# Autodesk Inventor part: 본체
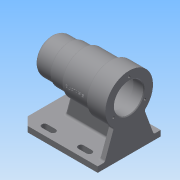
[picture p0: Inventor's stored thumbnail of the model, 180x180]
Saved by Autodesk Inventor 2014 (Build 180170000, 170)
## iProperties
Created: 2017-09
Part Number: 본체
Material: 일반
Document SubType Name: Modeling
Designer: net
Density: 1 g/cm^3
Appearance: 기본값
Author: net
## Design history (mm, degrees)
sketch "스케치1"
  geometry: L1 (56, 0)-(-56, 0); L2 (56, 0)-(56, 25); L3 (56, 25)-(31, 25); L4 (31, 25)-(31, 27); L5 (31, 27)-(11, 27); L6 (11, 27)-(11, 30); L7 (11, 30)-(-28, 30); L8 (-28, 30)-(-28, 34); L9 (-28, 34)-(-56, 34); L10 (-56, 21)-(-41, 21); L11 (-41, 21)-(-41, 21); L12 (-38, 24)-(10, 24); L13 (13, 21)-(13, 21); L14 (13, 21)-(24.7, 21); L15 (25, 20.7)-(25, 17.5); L16 (25, 17.5)-(42.7, 17.5); L17 (43, 17.2)-(43, 16); L18 (43, 16)-(46.7, 16); L19 (47, 15.7)-(47, 10.5); L20 (47, 10.5)-(47, 10.5); L21 (50, 7.5)-(50, 0); L22 (-56, 34)-(-56, 21); A1 r 0.3 centre (46.7, 15.7) between (47, 15.7) and (46.7, 16); A2 r 0.3 centre (42.7, 17.2) between (43, 17.2) and (42.7, 17.5); A3 r 3 centre (-38, 21) between (-38, 24) and (-41, 21); A4 r 3 centre (10, 21) between (13, 21) and (10, 24); A5 r 0.3 centre (24.7, 20.7) between (25, 20.7) and (24.7, 21); A6 r 3 centre (47, 7.5) between (50, 7.5) and (47, 10.5); 8 further points
  constraints: 44 end point, 15 point on line, 12 point on circle, 12 tangent, 10 parallel, 10 perpendicular, 6 centre point, 2 equal radius, 1 coincident, 1 horizontal, 1 midpoint
  dimensions: "d0" = 112 distance of L1.start L1.end; "d1" = 25 distance of L2.end L3.end; "d2" = 45 horizontal distance of L5.end L2.end; "d3" = 84 horizontal distance of L7.end L2.end; "d4" = 50 diameter of L2.end L1; "d5" = 54 diameter of L5 L1; "d6" = 60 diameter of L7 L1; "d7" = 68 diameter of L9 L1; "d11" = 15 distance of L10.start L10.end; "d12" = 54 distance of point (-41, 24) point (13, 24); "d13" = 12 distance of L13.end point (25, 21); "d14" = 18 distance of L15.end point (43, 17.5); "d15" = 4 distance of L17.end point (47, 16); "d16" = 3 distance of L19.end point (50, 10.5); "d17" = 48 diameter of L12 L1; "d18" = 42 diameter of L14 L1; "d19" = 21 diameter of L20 L1; "d20" = 32 diameter of L18 L1; "d21" = 35 diameter of L16 L1; "d22" = 42 diameter of L10 L1; "d23" = 112 horizontal distance of L9.end L2.end; "d66" = 3 radius of A3; "d77" = 0.3 radius of A5; "d80" = 0.3 radius of A2; "d81" = 3 radius of A6
revolve "회전1" sketch "스케치1" stored, may be unused: angle "d8" = 90 deg
sketch "스케치2"
  geometry: 1 further point
node "작업 평면1"
sketch "스케치3"
  geometry: L1 (-56, 25)-(-56, -25) reference; L2 (56, 34)-(56, -34) reference; L3 (-56, 45)-(56, 45); L4 (56, 45)-(56, -45); L5 (56, -45)-(-56, -45); L6 (-56, -45)-(-56, 45); 2 further points
  constraints: 8 end point, 2 midpoint, 2 parallel, 1 horizontal, 1 perpendicular
  dimensions: "d25" = 112 distance of L3.start L3.end; "d26" = 90 distance of L5.end L3.start
extrude "돌출1" join sketch "스케치3" distance "d27" = 8; taper "d28" = 0 deg
chamfer "모따기1" distance "d29" = 12; stored, may be unused: second distance "d30" = 2, angle "d31" = 45 deg
sketch "스케치4"
  geometry: L1 (56, 45)-(-44, 45) reference; L2 (20, 33)-(32, 33); L3 (20, 37)-(32, 37); L4 (32, 29)-(20, 29); A1 r 4 centre (20, 33) between (20, 37) and (20, 29); A2 r 4 centre (32, 33) between (32, 29) and (32, 37); 3 further points
  constraints: 8 end point, 4 point on circle, 4 tangent, 2 centre point, 2 parallel, 1 horizontal alignment, 1 midpoint
  dimensions: "d32" = 12 distance of L2.start L2.end; "d33" = 4 radius of A1; "d35" = 24 horizontal distance of L1.start L3.end
extrude "돌출2" cut sketch "스케치4" distance "d36" = 8; taper "d37" = 0 deg
sketch "스케치5"
  geometry: L1 (56, -45)-(56, 45) reference; L2 (-32, -4)-(56, -4); L3 (56, -4)-(56, 4); L4 (56, 4)-(-32, 4); L5 (-32, 4)-(-32, -4); 3 further points
  constraints: 8 end point, 3 midpoint, 2 parallel, 1 horizontal, 1 horizontal alignment, 1 perpendicular
  dimensions: "d41" = 88 distance of L2.start L2.end; "d42" = 8 distance of L4.end L2.start
extrude "돌출3" join sketch "스케치5" stored distance "d43" = 8; taper "d44" = 0 deg
sketch "스케치6"
  geometry: L1 (-8, 41)-(-36.236, 41) reference; L2 (-8, 0)-(-8, 41) reference; L3 (-8, 49)-(-8, 90) reference; L4 (-8, 49)-(-36.236, 49) reference; L5 (-43.992, 23.1)-(-8, 10); L6 (-43.992, 66.9)-(-8, 80); A1 r 34 centre (-70, 45) between (-36.236, 49) and (-36.236, 41) reference
  constraints: 4 end point, 2 point on circle, 2 point on line, 1 equal length
  dimensions: "d48" = 110 deg angle of L2 L5; "d50" = 110 deg angle of L3 L6; "d51" = 10 distance of L2.start L5.end
extrude "돌출4" join sketch "스케치6" distance "d52" = 8; taper "d53" = 0 deg
sketch "스케치7" dims "d54" = 52
  geometry: C1 r 21 at (-70, 45) reference; A1 r 34 centre (-70, 45) between (-43.992, 66.9) and (-43.992, 23.1) reference; 2 further points
  constraints: 2 horizontal alignment, 1 coincident, 2 other
hole "구멍1" sketch "스케치7" at (-96, 45) diameter "d55" = 3.242; stored, may be unused: countersink angle "d59" = 90 deg, drill point angle "d61" = 118 deg; dims "d56" = 8, "d57" = 4, "d58" = 2, "d60" = 11
chamfer "모따기2" distance "d67" = 1; stored, may be unused: second distance "d68" = 2, angle "d69" = 45 deg
fillet "모깎기1" dims "d70" = 3
sketch "스케치9"
  geometry: L1 (3.828, 35.298)-(21, 35.298) reference; L2 (0, 37.322)-(1, 37.322) reference; L3 (0, 0)-(0, 37.322) reference; L4 (88, 35.992)-(88, 0) reference; L5 (0, 0)-(9.458, 35.298); L6 (-12, 0)-(88, 0) reference; 1 further point
  constraints: 2 end point, 1 point on line, 1 other
  dimensions: "d71" = 105 deg angle of L6 L5
extrude "돌출5" cut sketch "스케치9" distance "d72" = 8; taper "d73" = 0 deg
fillet "모깎기2" dims "d74" = 3
fillet "모깎기3" dims "d75" = 3
fillet "모깎기4" dims "d76" = 3
sketch "스케치10"
  geometry: 1 further point
fillet "모깎기5" dims "d82" = 8
sketch "스케치11"
  geometry: 1 further point
node "작업 평면2"
sketch "스케치12"
  geometry: L1 (-27.5, 1.94)-(28.341, 1.94); L2 (28.341, 1.94)-(28.341, -2); L3 (28.341, -2)-(-27.5, -2); L4 (-27.5, -2)-(-27.5, 1.94); L5 (-47.5, -24.711)-(-47.5, 34) reference; L6 (52.5, -70)-(-47.5, -70) reference; 1 further point
  constraints: 2 other
  dimensions: "d84" = 68 distance between parallel lines of L6 L3; "d85" = 20 distance from line of L5 L1.start
feature "엠보싱1" sketch "스케치12" dims "d15" = 4, "d86" = 0.5, "d87" = 0
node "솔리드1"
pattern_linear "직사각형 패턴1" dims "d40" = 52
mirror "대칭1"
pattern_circular "원형 패턴1" dims angle "d63" = 360 deg
